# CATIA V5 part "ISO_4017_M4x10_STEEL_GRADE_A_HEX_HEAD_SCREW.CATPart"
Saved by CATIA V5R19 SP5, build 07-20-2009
Part number: ISO 4017 SCREW M4x10 STEEL GRADE A HEXAGON HEAD
Publications: "Mating Face", "Axis"
Bounding box of the stored display mesh (mm): x -10 to 2.925, y -3.5 to 3.5, z -4.041 to 4.041
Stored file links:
  Z:\UA\ATLAS\atlascar\ServoPiloto\dir\suportePotenciometro\potenciometro\ISO_4017_M4x10_STEEL_GRADE_A_HEX_HEAD_SCREW.CATPart
  Z:\programs_vbox\Dassault Systemes\B19\intel_a\startup\components\MechanicalStandardParts\EN_Standards\Design_Tables\EN_ISO_4017_GRADES_A_B_HEXAGON_HEAD_SCREW.txt
  Z:\programs_vbox\Dassault Systemes\B19\intel_a\startup\components\MechanicalStandardParts\ISO_Standards\Design_Tables\ISO_4017_GRADES_A_B_HEXAGON_HEAD_SCREW.txt
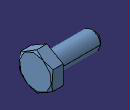
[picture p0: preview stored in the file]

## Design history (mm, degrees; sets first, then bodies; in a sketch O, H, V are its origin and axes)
Parameters
  Designation = "M4"
  d_dia = 4 mm
  l_length = 10 mm
  k_max_head_depth = 2.925 mm
  r_min = 0.2 mm
  s_nom_across_flats = 7 mm
  dw_min = 5.88 mm
  c_max = 0.4 mm
  P_pitch = 0.7 mm
  threading = 7.9 mm
Body1 "PartBody" (main body)
  Sketch1 on yz-plane, origin (0, 0, 0), H (0, 1, 0), V (0, 0, 1)
    circle A1 centre (0, 0) radius 2.94
    radius A1 = 2.94 {= dw_min /2}
  Pad1: profile Sketch1, direction (1, 0, 0), length 0.4 {= c_max}
  Sketch2 on face of Pad1, origin (0.4, 0, 0), H (0, 1, 0), V (0, 0, 1)
    point P1 (3.5, -2.0207)
    point P2 (3.5, 2.0207)
    point P3 (0, 4.0415)
    point P4 (-3.5, 2.0207)
    point P5 (-3.5, -2.0207)
    point P6 (0, -4.0415)
    point P7 (3.5, 0)
    line L1 (3.5, -2.0207) -> (3.5, 2.0207)
    line L2 (3.5, 2.0207) -> (0, 4.0415)
    line L3 (0, 4.0415) -> (-3.5, 2.0207)
    line L4 (-3.5, 2.0207) -> (-3.5, -2.0207)
    line L5 (-3.5, -2.0207) -> (0, -4.0415)
    line L6 (0, -4.0415) -> (3.5, -2.0207)
    construction line L7 (0, 0) -> (3.5, 0)
    construction circle A1 centre (0, 0) radius 4.0415
    construction arc A2 centre (-3.5, -2.0207) radius 4.0415 from (-3.5, 2.0207) to (0, -4.0415) cw
    construction arc A3 centre (3.5, 2.0207) radius 4.0415 from (0, 4.0415) to (3.5, -2.0207) ccw
    point P8 (-3.5, -2.0207)
    point P9 (3.5, 2.0207)
    distance L1 L4 = 7 {= s_nom_across_flats}
    horizontal: L7 H
    coincidence: A1 P1, A1 P2, A1 P3, A1 P4, A1 P5, A1 P6, A2 P4, A2 P6, A2 O, P8 P5, A3 P3, A3 P1, A3 O, P9 P2
    midpoint: P7 L1
  Pad2: profile Sketch2, direction (1, 0, 0), length 2.525 {= k_max_head_depth -c_max}
  Sketch3 on zx-plane, origin (0, 0, 0), H (-1, 0, 0), V (0, 0, 1)
    point P1 (-2.925, 3.4983)
    axis line L1 (-94.6904, 0) -> (76.7146, 0)
    reference intersected line E1 through (1000000, 0) direction (-1, 0) from xy-plane
    line L2 (-2.6114, 4.0415) -> (-2.925, 3.4983)
    line L3 (-2.6114, 4.0415) -> (-2.925, 4.0415)
    line L4 (-2.925, 4.0415) -> (-2.925, 3.4983)
    reference projected line E2 (-0.8, 4.0415) -> (-18.28, 4.0415) from edge [face of Pad2 | face of Pad2]
    distance P1 H = 3.4983 {= s_nom_across_flats /2.001}
    distance P1 V = 2.925 {= k_max_head_depth}
    angle L4 L2 = 30
    horizontal: L1 H, L3 H
    coincidence: L1 E1, L3 E2
    vertical: L4 V
  Groove1: profile Sketch3, axis Sketch3.L1, angle 360
  Sketch4 on face of Pad1, origin (0, 0, 0), H (0, -1, 0), V (0, 0, 1)
    circle A1 centre (0, 0) radius 1.9512
    radius A1 = 1.9512 {= d_dia /2.05}
  Pad3: profile Sketch4, direction (-1, 0, 0), length 10 {= l_length}
  Fillet1: radius 0.2 {= r_min}, on edge [face of Pad3 | face of Pad1]
  Chamfer1: length 0.7 {= P_pitch}, angle 45, on edge [face of Pad3 | face of Pad3]
  Thread1: diameter 3.9024 {= d_dia /1.025}, depth 7.9 {= threading}, pitch 1, on face of Pad3, from face of Pad3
